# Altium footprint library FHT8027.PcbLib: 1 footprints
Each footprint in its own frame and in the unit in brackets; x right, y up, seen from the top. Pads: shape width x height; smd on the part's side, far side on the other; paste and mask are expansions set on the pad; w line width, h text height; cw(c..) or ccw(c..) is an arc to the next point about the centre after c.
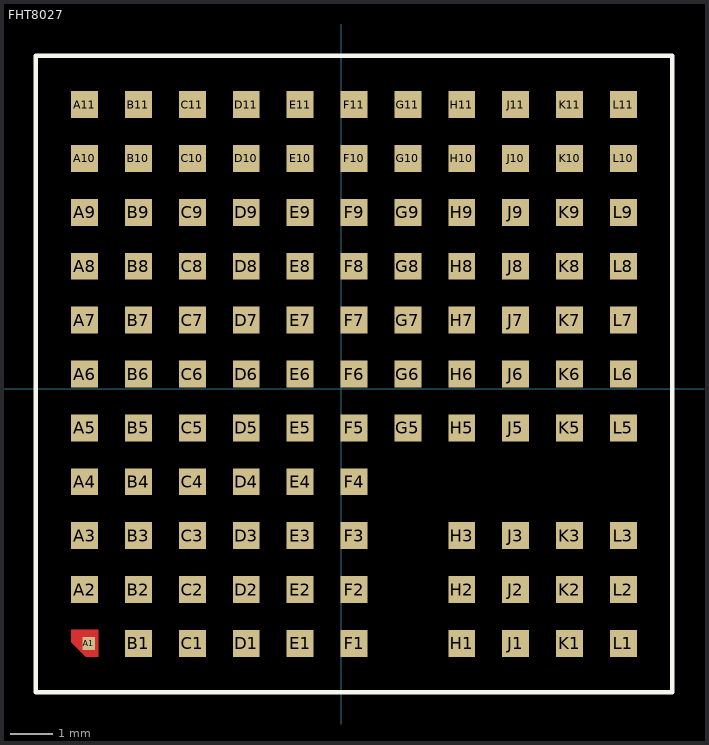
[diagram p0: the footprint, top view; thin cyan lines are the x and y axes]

## FHT8027 [mm]
pads (113):
  rect 0.3x0.3 smd mask+0: A1(-5.95,-6)
  rect 0.635x0.635 smd mask+0: A2(-6.05,-4.73) A3(-6.05,-3.46) A4(-6.05,-2.19) A5(-6.05,-0.92) A6(-6.05,0.35) A7(-6.05,1.62) A8(-6.05,2.89) A9(-6.05,4.16) A10(-6.05,5.43) A11(-6.05,6.7) B1(-4.78,-6) B2(-4.78,-4.73) B3(-4.78,-3.46) B4(-4.78,-2.19) B5(-4.78,-0.92) B6(-4.78,0.35) B7(-4.78,1.62) B8(-4.78,2.89) B9(-4.78,4.16) B10(-4.78,5.43) B11(-4.78,6.7) C1(-3.51,-6) C2(-3.51,-4.73) C3(-3.51,-3.46) C4(-3.51,-2.19) C5(-3.51,-0.92) C6(-3.51,0.35) C7(-3.51,1.62) C8(-3.51,2.89) C9(-3.51,4.16) C10(-3.51,5.43) C11(-3.51,6.7) D1(-2.24,-6) D2(-2.24,-4.73) D3(-2.24,-3.46) D4(-2.24,-2.19) D5(-2.24,-0.92) D6(-2.24,0.35) D7(-2.24,1.62) D8(-2.24,2.89) D9(-2.24,4.16) D10(-2.24,5.43) D11(-2.24,6.7) E1(-0.97,-6) E2(-0.97,-4.73) E3(-0.97,-3.46) E4(-0.97,-2.19) E5(-0.97,-0.92) E6(-0.97,0.35) E7(-0.97,1.62) E8(-0.97,2.89) E9(-0.97,4.16) E10(-0.97,5.43) E11(-0.97,6.7) F1(0.3,-6) F2(0.3,-4.73) F3(0.3,-3.46) F4(0.3,-2.19) F5(0.3,-0.92) F6(0.3,0.35) F7(0.3,1.62) F8(0.3,2.89) F9(0.3,4.16) F10(0.3,5.43) F11(0.3,6.7) G5(1.57,-0.92) G6(1.57,0.35) G7(1.57,1.62) G8(1.57,2.89) G9(1.57,4.16) G10(1.57,5.43) G11(1.57,6.7) H1(2.84,-6) H2(2.84,-4.73) H3(2.84,-3.46) H5(2.84,-0.92) H6(2.84,0.35) H7(2.84,1.62) H8(2.84,2.89) H9(2.84,4.16) H10(2.84,5.43) H11(2.84,6.7) J1(4.11,-6) J2(4.11,-4.73) J3(4.11,-3.46) J5(4.11,-0.92) J6(4.11,0.35) J7(4.11,1.62) J8(4.11,2.89) J9(4.11,4.16) J10(4.11,5.43) J11(4.11,6.7) K1(5.38,-6) K2(5.38,-4.73) K3(5.38,-3.46) K5(5.38,-0.92) K6(5.38,0.35) K7(5.38,1.62) K8(5.38,2.89) K9(5.38,4.16) K10(5.38,5.43) K11(5.38,6.7) L1(6.65,-6) L2(6.65,-4.73) L3(6.65,-3.46) L5(6.65,-0.92) L6(6.65,0.35) L7(6.65,1.62) L8(6.65,2.89) L9(6.65,4.16) L10(6.65,5.43) L11(6.65,6.7)
Top Layer:
  region: -5.733,-5.683 -6.366,-5.683 -6.366,-5.976 -6.026,-6.316 -5.733,-6.316
Top Overlay:
  lines w0.1: -7.2,-7.15 7.8,-7.15 7.8,7.85 -7.2,7.85 -7.2,-7.15
3D body "FHT8027.STEP": height 4.33, standoff -0.01, extent -7.191,-7.146 7.809,7.854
